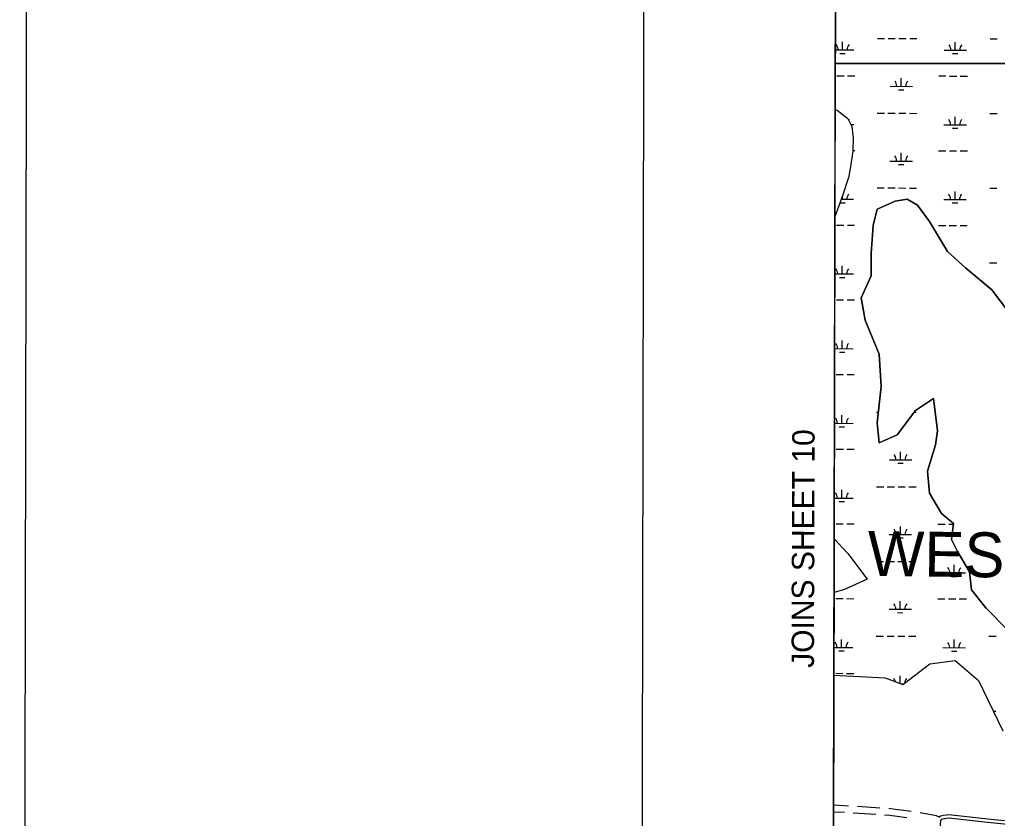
# Model space of a CAD drawing. Extents: x 3192952 to 3230831, y 849296 to 874698.
# Drawn here: x 3193535 to 3197892, y 862258 to 865816 of the extents above; entities that cross this region are included whole.
import ezdxf

# ---------------------------------------------------------------- set-up
doc = ezdxf.new("R2010")
doc.units = 0
for name, color, linetype in [('G-ANNO-NPLT', 7, 'Continuous'), ('V-ANNO-SYMB', 7, 'Continuous'), ('V-ANNO-TEXT', 7, 'Continuous'), ('V-GRID-FRAM', 7, 'Continuous'), ('V-ROAD-CNTR', 7, 'Continuous'), ('V-SITE-VEGE', 7, 'Continuous'), ('V-TOPO-GNAM-IDEN', 7, 'Continuous'), ('V-TOPO-SHOR', 7, 'Continuous'), ('V-WETL-SWMP', 7, 'Continuous')]:
    doc.layers.add(name, color=color, linetype=linetype)

msp = doc.modelspace()

# ---------------------------------------------------------------- linework, layer by layer
at = {"layer": 'G-ANNO-NPLT'}
msp.add_lwpolyline([(3193535.2, 849948.4), (3230201.8, 849879.1), (3230247.5, 874045.7), (3193580.9, 874115)], close=True, dxfattribs=at)
at = {"layer": 'V-ANNO-SYMB'}
msp.add_lwpolyline([(3196286.6, 850568.3), (3229369.7, 850505.7), (3229413, 873422.2), (3196329.9, 873484.8), (3196286.6, 850568.3)], dxfattribs=at)
at = {"layer": 'V-GRID-FRAM'}
msp.add_lwpolyline([(3197186.7, 872920.9), (3228554.1, 872861.6), (3228527.7, 854674), (3197144.3, 854733.3), (3197186.7, 872920.9)], dxfattribs=at)
at = {"layer": 'V-ROAD-CNTR'}
for p, q in [((3197209.9, 862283.7), (3197161.3, 862285.9)), ((3197228.7, 862312.9), (3197162.6, 862315.9)), ((3197349.6, 862275), (3197249.8, 862281.5)), ((3197368.4, 862303.8), (3197268.7, 862310.4))]:
    msp.add_line(p, q, dxfattribs=at)
for points in [[(3198928.2, 863395.3), (3198858.9, 863297.3), (3198724.8, 863111.2), (3198637.8, 862992.9), (3198546.7, 862873.6), (3198423, 862713.7), (3198317.9, 862568.4), (3198212, 862430.1), (3198141.8, 862342.8), (3198073.9, 862265), (3198054.2, 862249.7), (3198027.6, 862231.1), (3197996.3, 862224.5), (3197847.1, 862239.6), (3197674.7, 862258.1), (3197665.3, 862257.1), (3197654.4, 862255.9), (3197644.8, 862253.5), (3197639.4, 862249.4), (3197637.6, 862248.8), (3197636.5, 862229.7), (3197644.5, 862208), (3197659.5, 862186.7)], [(3198910.5, 863396.3), (3198846.7, 863306), (3198712.7, 863120.1), (3198625.8, 863001.9), (3198534.8, 862882.8), (3198411, 862722.7), (3198305.9, 862577.3), (3198200.2, 862439.4), (3198130.3, 862352.5), (3198063.6, 862276), (3198045.3, 862261.8), (3198021.5, 862245.2), (3197995.5, 862239.7), (3197848.7, 862254.5), (3197674.7, 862273.2), (3197665.5, 862272.2)], [(3197507.5, 862287.9), (3197415, 862300.7), (3197408.4, 862301.2)], [(3197631.6, 862262.9), (3197627.1, 862266.2), (3197620.9, 862269.1), (3197547, 862282)], [(3197488.7, 862260.3), (3197412, 862270.9), (3197389.5, 862272.4)], [(3197665.5, 862272.2), (3197663.7, 862272), (3197651.8, 862270.7), (3197638.1, 862267.3), (3197632.4, 862262.9), (3197631.5, 862262.6)]]:
    msp.add_lwpolyline(points, dxfattribs=at)
at = {"layer": 'V-SITE-VEGE'}
for p, q in [((3197173.7, 867334.2), (3197169.7, 865620.5)), ((3197169.7, 865620.5), (3197160.1, 861523.5)), ((3197169.7, 865620.5), (3199651, 865620.5)), ((3200096.1, 865620.5), (3197169.7, 865620.5)), ((3197355.9, 864970.5), (3197436.6, 865006.4)), ((3197436.6, 865006.4), (3197490.3, 865015.4)), ((3197490.3, 865015.4), (3197535.1, 864988.5)), ((3197535.1, 864988.5), (3197588.9, 864916.7)), ((3197338, 864898.8), (3197355.9, 864970.5)), ((3197329, 864773.3), (3197338, 864898.8)), ((3197588.9, 864916.7), (3197669.5, 864782.2)), ((3197329, 864674.6), (3197329, 864773.3)), ((3197669.5, 864782.2), (3197750.2, 864710.5)), ((3197284.2, 864576), (3197329, 864674.6)), ((3197750.2, 864710.5), (3197866.7, 864611.8)), ((3197866.7, 864611.8), (3197983.2, 864459.4)), ((3197302.2, 864477.3), (3197284.2, 864576)), ((3197364.9, 864324.9), (3197302.2, 864477.3)), ((3197373.8, 864181.4), (3197364.9, 864324.9)), ((3197355.9, 864020), (3197373.8, 864181.4)), ((3197606.8, 864127.6), (3197526.2, 864073.8)), ((3197624.7, 863984.1), (3197606.8, 864127.6)), ((3197526.2, 864073.8), (3197445.5, 863966.2)), ((3197364.9, 863930.3), (3197355.9, 864020)), ((3197615.8, 863921.3), (3197624.7, 863984.1)), ((3197445.5, 863966.2), (3197364.9, 863930.3)), ((3197579.9, 863804.8), (3197615.8, 863921.3)), ((3197588.9, 863706.1), (3197579.9, 863804.8)), ((3197642.7, 863616.4), (3197588.9, 863706.1)), ((3197696.4, 863571.6), (3197642.7, 863616.4)), ((3197687.5, 863499.9), (3197696.4, 863571.6)), ((3197714.3, 863446), (3197687.5, 863499.9)), ((3197768.1, 863356.4), (3197714.3, 863446)), ((3197777.1, 863275.7), (3197768.1, 863356.4)), ((3197839.8, 863195), (3197777.1, 863275.7)), ((3197938.4, 863096.3), (3197839.8, 863195))]:
    msp.add_line(p, q, dxfattribs=at)
at = {"layer": 'V-TOPO-SHOR'}
for points in [[(3197750.2, 864710.5), (3197669.5, 864782.2), (3197588.9, 864916.7), (3197535.1, 864988.5), (3197490.3, 865015.4), (3197436.6, 865006.4), (3197355.9, 864970.5), (3197338, 864898.8), (3197329, 864773.3), (3197329, 864674.6), (3197284.2, 864576), (3197302.2, 864477.3), (3197364.9, 864324.9), (3197373.8, 864181.4), (3197355.9, 864020), (3197364.9, 863930.3), (3197445.5, 863966.2), (3197526.2, 864073.8), (3197606.8, 864127.6), (3197624.7, 863984.1), (3197615.8, 863921.3), (3197579.9, 863804.8), (3197588.9, 863706.1), (3197642.7, 863616.4), (3197696.4, 863571.6), (3197687.5, 863499.9), (3197714.3, 863446), (3197768.1, 863356.4), (3197777.1, 863275.7), (3197839.8, 863195), (3197938.4, 863096.3)], [(3197983.2, 864459.4), (3197866.7, 864611.8), (3197750.2, 864710.5)]]:
    msp.add_lwpolyline(points, dxfattribs=at)
at = {"layer": 'V-WETL-SWMP'}
for p, q in [((3197171.2, 866259.8), (3197169.2, 865415.7)), ((3197357, 865731), (3197389, 865731)), ((3197405, 865730.9), (3197437, 865730.9)), ((3197453, 865730.8), (3197485, 865730.8)), ((3197501, 865730.7), (3197533, 865730.7)), ((3197858.9, 865730.1), (3197890.9, 865730)), ((3197169.8, 865680.6), (3197252.3, 865680.5)), ((3197202.3, 865680.6), (3197202.3, 865716.6)), ((3197654.2, 865679.7), (3197754.2, 865679.5)), ((3197704.2, 865679.6), (3197704.2, 865715.6)), ((3197190.2, 865665.2), (3197214.2, 865665.1)), ((3197692.1, 865664.2), (3197716.1, 865664.2)), ((3197176.6, 865565.2), (3197208.6, 865565.1)), ((3197224.6, 865565.1), (3197256.6, 865565)), ((3197463.4, 865518.2), (3197463.5, 865554.2)), ((3197630.5, 865564.3), (3197662.5, 865564.3)), ((3197678.5, 865564.2), (3197710.5, 865564.2)), ((3197726.5, 865564.1), (3197758.5, 865564.1)), ((3197413.4, 865518.3), (3197513.4, 865518.1)), ((3197451.4, 865502.8), (3197475.4, 865502.8)), ((3197169.2, 865415.7), (3197177.3, 865412.1)), ((3197177.3, 865412.1), (3197225.4, 865375.4)), ((3197225.4, 865375.4), (3197242.5, 865339.2)), ((3197356.3, 865398.3), (3197388.3, 865398.3)), ((3197404.3, 865398.3), (3197436.3, 865398.2)), ((3197452.3, 865398.2), (3197484.3, 865398.1)), ((3197500.3, 865398.1), (3197532.3, 865398)), ((3197703.5, 865346.9), (3197703.6, 865382.9)), ((3197858.2, 865397.4), (3197890.2, 865397.3)), ((3197238.4, 865347.8), (3197251.6, 865347.8)), ((3197242.5, 865339.2), (3197249.5, 865289.3)), ((3197653.5, 865347), (3197753.5, 865346.9)), ((3197691.5, 865331.5), (3197715.5, 865331.5)), ((3197249.5, 865289.3), (3197247.1, 865229.9)), ((3197247.1, 865229.9), (3197235.4, 865151.2)), ((3197247.2, 865232.4), (3197256, 865232.4)), ((3197462.8, 865185.5), (3197462.8, 865221.5)), ((3197629.9, 865231.7), (3197661.9, 865231.6)), ((3197677.9, 865231.6), (3197709.9, 865231.5)), ((3197725.9, 865231.5), (3197757.9, 865231.4)), ((3197412.8, 865185.6), (3197512.8, 865185.4)), ((3197450.7, 865170.1), (3197474.7, 865170.1)), ((3197228, 865111.5), (3197202.9, 865035.1)), ((3197235.4, 865151.2), (3197228, 865111.5)), ((3197202.9, 865035.1), (3197168.1, 864937.5)), ((3197201, 865015.2), (3197201, 865030)), ((3197355.7, 865065.7), (3197387.7, 865065.6)), ((3197403.7, 865065.6), (3197435.7, 865065.5)), ((3197451.7, 865065.5), (3197483.7, 865065.4)), ((3197499.7, 865065.4), (3197531.7, 865065.3)), ((3197702.9, 865014.3), (3197703, 865050.3)), ((3197857.6, 865064.7), (3197889.6, 865064.7)), ((3197190.3, 864999.8), (3197213, 864999.8)), ((3197195.8, 865015.2), (3197251, 865015.1)), ((3197355.9, 864970.5), (3197436.6, 865006.4)), ((3197436.6, 865006.4), (3197490.3, 865015.4)), ((3197490.3, 865015.4), (3197535.1, 864988.5)), ((3197535.1, 864988.5), (3197588.9, 864916.7)), ((3197652.9, 865014.4), (3197752.9, 865014.2)), ((3197690.9, 864998.9), (3197714.9, 864998.8)), ((3197168.1, 864937.5), (3197164.7, 863502.9)), ((3197338, 864898.8), (3197355.9, 864970.5)), ((3197175.4, 864899.8), (3197207.4, 864899.8)), ((3197223.4, 864899.7), (3197255.4, 864899.7)), ((3197329, 864773.3), (3197338, 864898.8)), ((3197588.9, 864916.7), (3197669.5, 864782.2)), ((3197629.3, 864899), (3197661.3, 864898.9)), ((3197677.3, 864898.9), (3197709.3, 864898.8)), ((3197725.3, 864898.8), (3197757.3, 864898.7)), ((3197329, 864674.6), (3197329, 864773.3)), ((3197669.5, 864782.2), (3197750.2, 864710.5)), ((3197200.4, 864682.5), (3197200.4, 864718.5)), ((3197857, 864732), (3197889, 864732)), ((3197167.5, 864682.6), (3197250.4, 864682.5)), ((3197284.2, 864576), (3197329, 864674.6)), ((3197750.2, 864710.5), (3197866.7, 864611.8)), ((3197188.4, 864667.1), (3197212.4, 864667.1)), ((3197866.7, 864611.8), (3197983.2, 864459.4)), ((3197174.8, 864567.2), (3197206.8, 864567.1)), ((3197222.8, 864567.1), (3197254.8, 864567)), ((3197302.2, 864477.3), (3197284.2, 864576)), ((3197364.9, 864324.9), (3197302.2, 864477.3)), ((3197199.8, 864349.9), (3197199.8, 864385.9)), ((3197166.7, 864349.9), (3197249.8, 864349.8)), ((3197187.7, 864334.5), (3197211.7, 864334.4)), ((3197373.8, 864181.4), (3197364.9, 864324.9)), ((3197174.1, 864234.5), (3197206.1, 864234.4)), ((3197222.1, 864234.4), (3197254.1, 864234.3)), ((3197355.9, 864020), (3197373.8, 864181.4)), ((3197606.8, 864127.6), (3197526.2, 864073.8)), ((3197624.7, 863984.1), (3197606.8, 864127.6)), ((3197353.8, 864067.6), (3197361.2, 864067.6)), ((3197526.2, 864073.8), (3197445.5, 863966.2)), ((3197521.3, 864067.3), (3197529.8, 864067.3)), ((3197199.1, 864017.2), (3197199.2, 864053.2)), ((3197165.9, 864017.3), (3197249.1, 864017.1)), ((3197187.1, 864001.8), (3197211.1, 864001.7)), ((3197364.9, 863930.3), (3197355.9, 864020)), ((3197615.8, 863921.3), (3197624.7, 863984.1)), ((3197445.5, 863966.2), (3197364.9, 863930.3)), ((3197173.5, 863901.8), (3197205.5, 863901.8)), ((3197221.5, 863901.7), (3197253.5, 863901.7)), ((3197460.3, 863854.8), (3197460.3, 863890.8)), ((3197579.9, 863804.8), (3197615.8, 863921.3)), ((3197410.3, 863854.9), (3197510.3, 863854.7)), ((3197448.2, 863839.4), (3197472.2, 863839.4)), ((3197588.9, 863706.1), (3197579.9, 863804.8)), ((3197198.5, 863684.5), (3197198.6, 863720.5)), ((3197353.2, 863735), (3197385.2, 863734.9)), ((3197401.2, 863734.9), (3197433.2, 863734.8)), ((3197449.2, 863734.8), (3197481.2, 863734.7)), ((3197497.2, 863734.7), (3197529.2, 863734.6)), ((3197165.2, 863684.6), (3197248.5, 863684.4)), ((3197642.7, 863616.4), (3197588.9, 863706.1)), ((3197186.5, 863669.1), (3197210.5, 863669.1)), ((3197696.4, 863571.6), (3197642.7, 863616.4)), ((3197172.9, 863569.1), (3197204.9, 863569.1)), ((3197220.9, 863569.1), (3197252.9, 863569)), ((3197459.6, 863522.2), (3197459.7, 863558.2)), ((3197626.8, 863568.3), (3197658.8, 863568.2)), ((3197674.8, 863568.2), (3197696, 863568.2)), ((3197687.5, 863499.9), (3197696.4, 863571.6)), ((3197164.7, 863502.9), (3197225.3, 863437.5)), ((3197409.6, 863522.3), (3197509.6, 863522.1)), ((3197447.6, 863506.8), (3197471.6, 863506.7)), ((3197714.3, 863446), (3197687.5, 863499.9)), ((3197225.3, 863437.5), (3197311.8, 863323.3)), ((3197768.1, 863356.4), (3197714.3, 863446)), ((3197352.6, 863402.3), (3197384.6, 863402.2)), ((3197400.6, 863402.2), (3197432.6, 863402.1)), ((3197448.6, 863402.1), (3197480.6, 863402.1)), ((3197496.6, 863402), (3197528.6, 863402)), ((3197699.8, 863350.9), (3197699.8, 863386.9)), ((3197311.8, 863323.3), (3197209.9, 863277.3)), ((3197649.8, 863351), (3197749.8, 863350.8)), ((3197687.7, 863335.5), (3197711.7, 863335.4)), ((3197777.1, 863275.7), (3197768.1, 863356.4)), ((3197164.2, 863263.8), (3197163.3, 862896)), ((3197209.9, 863277.3), (3197164.2, 863263.8)), ((3197172.2, 863236.5), (3197204.2, 863236.4)), ((3197220.2, 863236.4), (3197252.2, 863236.3)), ((3197839.8, 863195), (3197777.1, 863275.7)), ((3197459, 863189.5), (3197459.1, 863225.5)), ((3197626.1, 863235.6), (3197658.1, 863235.5)), ((3197674.1, 863235.5), (3197706.1, 863235.5)), ((3197722.1, 863235.4), (3197754.1, 863235.4)), ((3197938.4, 863096.3), (3197839.8, 863195)), ((3197409, 863189.6), (3197509, 863189.4)), ((3197447, 863174.1), (3197471, 863174)), ((3197351.9, 863069.6), (3197383.9, 863069.6)), ((3197399.9, 863069.5), (3197431.9, 863069.5)), ((3197447.9, 863069.4), (3197479.9, 863069.4)), ((3197495.9, 863069.4), (3197527.9, 863069.3)), ((3197853.8, 863068.7), (3197885.8, 863068.6)), ((3197163.6, 863019.2), (3197247.2, 863019.1)), ((3197197.2, 863019.2), (3197197.3, 863055.2)), ((3197699.1, 863018.2), (3197699.2, 863054.2)), ((3197185.2, 863003.8), (3197209.2, 863003.7)), ((3197649.1, 863018.3), (3197749.1, 863018.1)), ((3197687.1, 863002.8), (3197711.1, 863002.8)), ((3197469.8, 862854), (3197591, 862945.9)), ((3197591, 862945.9), (3197703.5, 862960.3)), ((3197703.5, 862960.3), (3197807.6, 862872.6)), ((3197163.3, 862896), (3197392.3, 862883.7)), ((3197171.6, 862903.8), (3197203.6, 862903.7)), ((3197219.6, 862903.7), (3197251.6, 862903.6)), ((3197458.4, 862858.4), (3197458.4, 862892.8)), ((3197392.3, 862883.7), (3197469.8, 862854)), ((3197462.6, 862856.8), (3197473.5, 862856.8)), ((3197807.6, 862872.6), (3197915.6, 862647.8)), ((3197873.2, 862736), (3197885.2, 862735.9))]:
    msp.add_line(p, q, dxfattribs=at)
for centre, start, end in [((3197147, 865681.2), 359.1198, 40.6635), ((3197257.5, 865680.9), 139.1198, 180.6635), ((3197648.9, 865680.2), 359.1198, 40.6635), ((3197759.4, 865680), 139.1198, 180.6635), ((3197408.2, 865518.8), 359.1198, 40.6635), ((3197518.6, 865518.6), 139.1198, 180.6635), ((3197256.9, 865348.3), 139.1198, 143.8937), ((3197648.3, 865347.5), 359.1198, 40.6635), ((3197758.8, 865347.3), 139.1198, 180.6635), ((3197407.5, 865186.1), 359.1198, 40.6635), ((3197518, 865185.9), 139.1198, 180.6635), ((3197256.3, 865015.6), 139.1198, 180.6635), ((3197647.7, 865014.9), 359.1198, 40.6635), ((3197758.2, 865014.6), 139.1198, 180.6635), ((3197145.1, 864683.1), 359.1198, 40.6635), ((3197255.6, 864682.9), 139.1198, 180.6635), ((3197144.5, 864350.5), 359.1198, 40.6635), ((3197255, 864350.2), 139.1198, 180.6635), ((3197143.9, 864017.8), 359.1198, 40.6635), ((3197254.4, 864017.6), 139.1198, 180.6635), ((3197405, 863855.4), 359.1198, 40.6635), ((3197515.5, 863855.2), 139.1198, 180.6635), ((3197143.3, 863685.1), 359.1198, 40.6635), ((3197253.7, 863684.9), 139.1198, 180.6635), ((3197404.4, 863522.7), 359.1198, 40.6635), ((3197514.9, 863522.5), 139.1198, 180.6635), ((3197644.5, 863351.5), 359.1198, 40.6635), ((3197755, 863351.3), 139.1198, 180.6635), ((3197403.8, 863190.1), 359.1198, 40.6635), ((3197514.2, 863189.9), 139.1198, 180.6635), ((3197142, 863019.8), 359.1198, 40.6635), ((3197252.5, 863019.5), 139.1198, 180.6635), ((3197643.9, 863018.8), 359.1198, 40.6635), ((3197754.4, 863018.6), 139.1198, 180.6635), ((3197403.1, 862857.4), 15.0329, 40.6635), ((3197513.6, 862857.2), 139.1198, 174.4087)]:
    msp.add_arc(centre, 35.2, start, end, dxfattribs=at)

# ---------------------------------------------------------------- texts
at = {"layer": 'V-ANNO-TEXT'}
msp.add_text('JOINS SHEET 10', height=100, rotation=89.8417, dxfattribs=at).set_placement((3197074.6, 862928.1))
at = {"layer": 'V-TOPO-GNAM-IDEN'}
msp.add_text('WEST', height=200, rotation=359.2712, dxfattribs=at).set_placement((3197312.9, 863338.3))

doc.saveas('drawing.dxf')
